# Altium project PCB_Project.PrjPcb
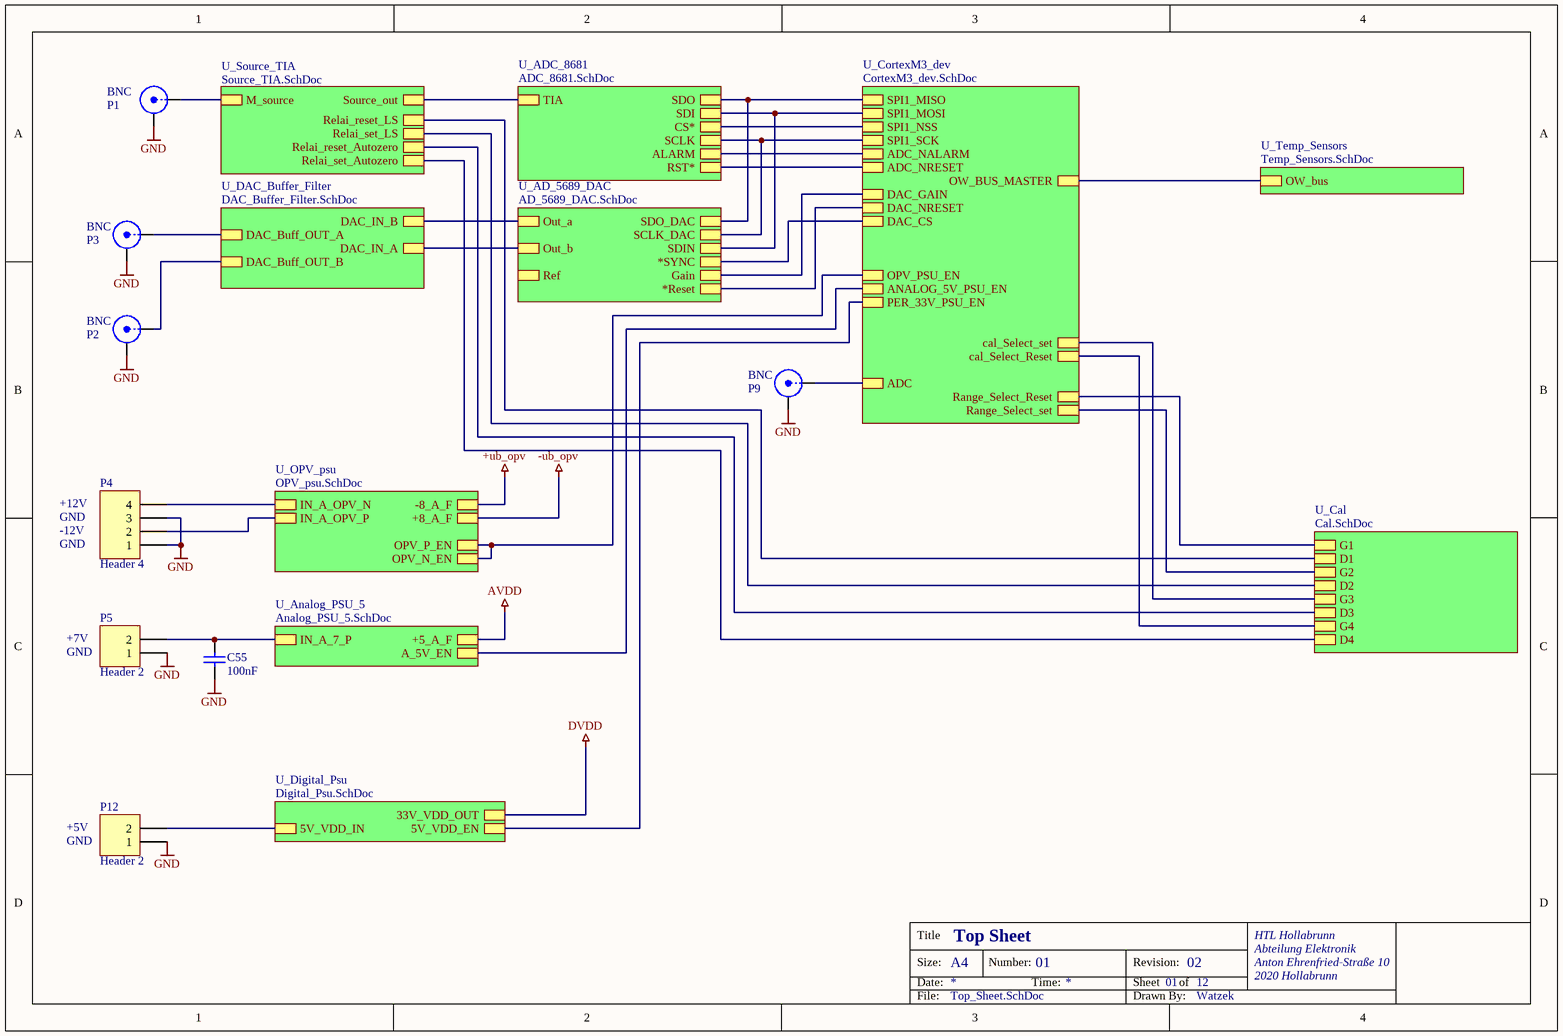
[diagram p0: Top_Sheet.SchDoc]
11 sheets, 114 parts. Net scope: hierarchical (ports join the sheet entries above them; power ports are global).
Board file: PCB1.PcbDoc
Sheets:
  Top_Sheet.SchDoc
    U_Source_TIA = Source_TIA.SchDoc
    U_DAC_Buffer_Filter = DAC_Buffer_Filter.SchDoc
    U_ADC_8681 = ADC_8681.SchDoc
    U_AD_5689_DAC = AD_5689_DAC.SchDoc
    U_Temp_Sensors = Temp_Sensors.SchDoc
    U_Digital_Psu = Digital_Psu.SchDoc
    U_Analog_PSU_5 = Analog_PSU_5.SchDoc
    U_OPV_psu = OPV_psu.SchDoc
    U_CortexM3_dev = CortexM3_dev.SchDoc
    U_Cal = Cal.SchDoc

## Sheet Top_Sheet.SchDoc: Top Sheet
size A4; ApprovedBy: Watzek; CheckedBy: Watzek; Author: Watzek; DrawnBy: Watzek; Organization: HTL Hollabrunn; Address1: Abteilung Elektronik; Address2: Anton Ehrenfried-Straße 10; Address3: 2020 Hollabrunn; DocumentNumber: 01; Revision: 02; SheetNumber: 01; SheetTotal: 12; SPICEModelCacheIHPBHSPQ: <root> / <DocumentId>IHPBHSPQ</DocumentId> / <CacheFrame Number="0"> / <Model Name="cap" Kind="MDL"> / <Text>*Default semiconductor capacitor / .MODEL CAP C()</Text> / </Model> / </CacheFrame> / </root>

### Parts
C55  100nF  [C1206-KUE]
P1  BNC  [BNC_RA CON]
P2  BNC  [BNC_RA CON]
P3  BNC  [BNC_RA CON]
P4  Header 4  [HDR1X4]
P5  Header 2  [HDR1X2]
P9  BNC  [BNC_RA CON]
P12  Header 2  [HDR1X2]

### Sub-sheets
U_AD_5689_DAC = AD_5689_DAC.SchDoc: Ref, Out_a, Out_b, SDIN, SDO_DAC, SCLK_DAC, *SYNC, Gain, *Reset
U_ADC_8681 = ADC_8681.SchDoc: SDI, CS*, SCLK, SDO, ALARM, RST*, TIA
U_Analog_PSU_5 = Analog_PSU_5.SchDoc: IN_A_7_P, +5_A_F, A_5V_EN
U_Cal = Cal.SchDoc: G1, G2, D1, D2, G3, D3, G4, D4
U_CortexM3_dev = CortexM3_dev.SchDoc: SPI1_NSS, SPI1_SCK, SPI1_MISO, SPI1_MOSI, ADC_NALARM, ADC_NRESET, DAC_GAIN, DAC_NRESET, DAC_CS, OW_BUS_MASTER, OPV_PSU_EN, ANALOG_5V_PSU_EN, PER_33V_PSU_EN, Range_Select_set, Range_Select_Reset, ADC, cal_Select_Reset, cal_Select_set
U_DAC_Buffer_Filter = DAC_Buffer_Filter.SchDoc: DAC_IN_B, DAC_Buff_OUT_B, DAC_IN_A, DAC_Buff_OUT_A
U_Digital_Psu = Digital_Psu.SchDoc: 5V_VDD_IN, 33V_VDD_OUT, 5V_VDD_EN
U_OPV_psu = OPV_psu.SchDoc: IN_A_OPV_P, +8_A_F, IN_A_OPV_N, -8_A_F, OPV_P_EN, OPV_N_EN
U_Source_TIA = Source_TIA.SchDoc: M_source, Source_out, Relai_set_LS, Relai_reset_LS, Relai_reset_Autozero, Relai_set_Autozero
U_Temp_Sensors = Temp_Sensors.SchDoc: OW_bus

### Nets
GND: C55.1 P1.2(Y) P2.2(Y) P3.2(Y) P4.1 P4.3 P5.1 P9.2(Y) P12.1
M_source: P1.1(X) ; sheet U_Source_TIA/M_source
SPI1_MISO: sheet U_ADC_8681/SDO, sheet U_AD_5689_DAC/SDO_DAC, sheet U_CortexM3_dev/SPI1_MISO
SPI1_MOSI: sheet U_ADC_8681/SDI, sheet U_AD_5689_DAC/SDIN, sheet U_CortexM3_dev/SPI1_MOSI
SPI1_SCK: sheet U_ADC_8681/SCLK, sheet U_AD_5689_DAC/SCLK_DAC, sheet U_CortexM3_dev/SPI1_SCK
NetC36_2: P12.2 ; sheet U_Digital_Psu/5V_VDD_IN
NetC47_2: P4.2 ; sheet U_OPV_psu/IN_A_OPV_P
NetC49_2: P4.4 ; sheet U_OPV_psu/IN_A_OPV_N
NetC55_2: C55.2 P5.2 ; sheet U_Analog_PSU_5/IN_A_7_P
NetD5_2: sheet U_Source_TIA/Relai_set_LS, sheet U_Cal/D2
NetD6_2: sheet U_Source_TIA/Relai_reset_LS, sheet U_Cal/D1
NetD7_2: sheet U_Source_TIA/Relai_reset_Autozero, sheet U_Cal/D3
NetD8_2: sheet U_Source_TIA/Relai_set_Autozero, sheet U_Cal/D4
NetN3_7: sheet U_Source_TIA/Source_out, sheet U_ADC_8681/TIA
NetN3_11: sheet U_ADC_8681/CS*, sheet U_CortexM3_dev/SPI1_NSS
NetN3_14: sheet U_ADC_8681/ALARM, sheet U_CortexM3_dev/ADC_NALARM
NetN4_1: sheet U_AD_5689_DAC/*Reset, sheet U_CortexM3_dev/DAC_NRESET
NetN4_2: P9.1(X) ; sheet U_CortexM3_dev/ADC
NetN4_3: sheet U_AD_5689_DAC/*SYNC, sheet U_CortexM3_dev/DAC_CS
NetN4_4: sheet U_AD_5689_DAC/Gain, sheet U_CortexM3_dev/DAC_GAIN
NetN4_9: sheet U_CortexM3_dev/cal_Select_set, sheet U_Cal/G3
NetN4_10: sheet U_CortexM3_dev/cal_Select_Reset, sheet U_Cal/G4
NetN4_11: sheet U_CortexM3_dev/Range_Select_set, sheet U_Cal/G2
NetN4_12: sheet U_CortexM3_dev/Range_Select_Reset, sheet U_Cal/G1
NetN4_13: sheet U_OPV_psu/OPV_P_EN, sheet U_OPV_psu/OPV_N_EN, sheet U_CortexM3_dev/OPV_PSU_EN
NetN4_20: sheet U_Analog_PSU_5/A_5V_EN, sheet U_CortexM3_dev/ANALOG_5V_PSU_EN
NetN4_21: sheet U_Temp_Sensors/OW_bus, sheet U_CortexM3_dev/OW_BUS_MASTER
NetN4_23: sheet U_Digital_Psu/5V_VDD_EN, sheet U_CortexM3_dev/PER_33V_PSU_EN
NetN4_27: sheet U_ADC_8681/RST*, sheet U_CortexM3_dev/ADC_NRESET
NetP2_1: P2.1(X) ; sheet U_DAC_Buffer_Filter/DAC_Buff_OUT_B
NetP3_1: P3.1(X) ; sheet U_DAC_Buffer_Filter/DAC_Buff_OUT_A
NetR19_1: sheet U_DAC_Buffer_Filter/DAC_IN_B, sheet U_AD_5689_DAC/Out_a
NetR20_1: sheet U_DAC_Buffer_Filter/DAC_IN_A, sheet U_AD_5689_DAC/Out_b

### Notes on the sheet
- +12V
- GND
- -12V
- +7V
- +5V

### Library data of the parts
C55 = Capacitor: Manufacturer: Kemet; Bezeichnung: Kerko +-10% 63V
P1-P3 P9 = BNC: BNC Elbow Connector
P4 = Header 4: Header, 4-Pin
P5 P12 = Header 2: Header, 2-Pin

## Sheet Source_TIA.SchDoc: TIA and damper
size A4; Author: Watzek; DrawnBy: Watzek; Organization: HTL Hollabrunn; Address1: Abteilung Elektronik; Address2: Anton Ehrenfried-Straße 10; Address3: 2020 Hollabrunn; DocumentNumber: 02; Revision: 02; SheetNumber: 02; SheetTotal: 12; SPICEModelCacheBSQSHVBX: <root> / <DocumentId>BSQSHVBX</DocumentId> / <CacheFrame Number="0"> / <Model Name="cap" Kind="MDL"> / <Text>*Default semiconductor capacitor / .MODEL CAP C()</Text> / </Model> / </CacheFrame> / </root>
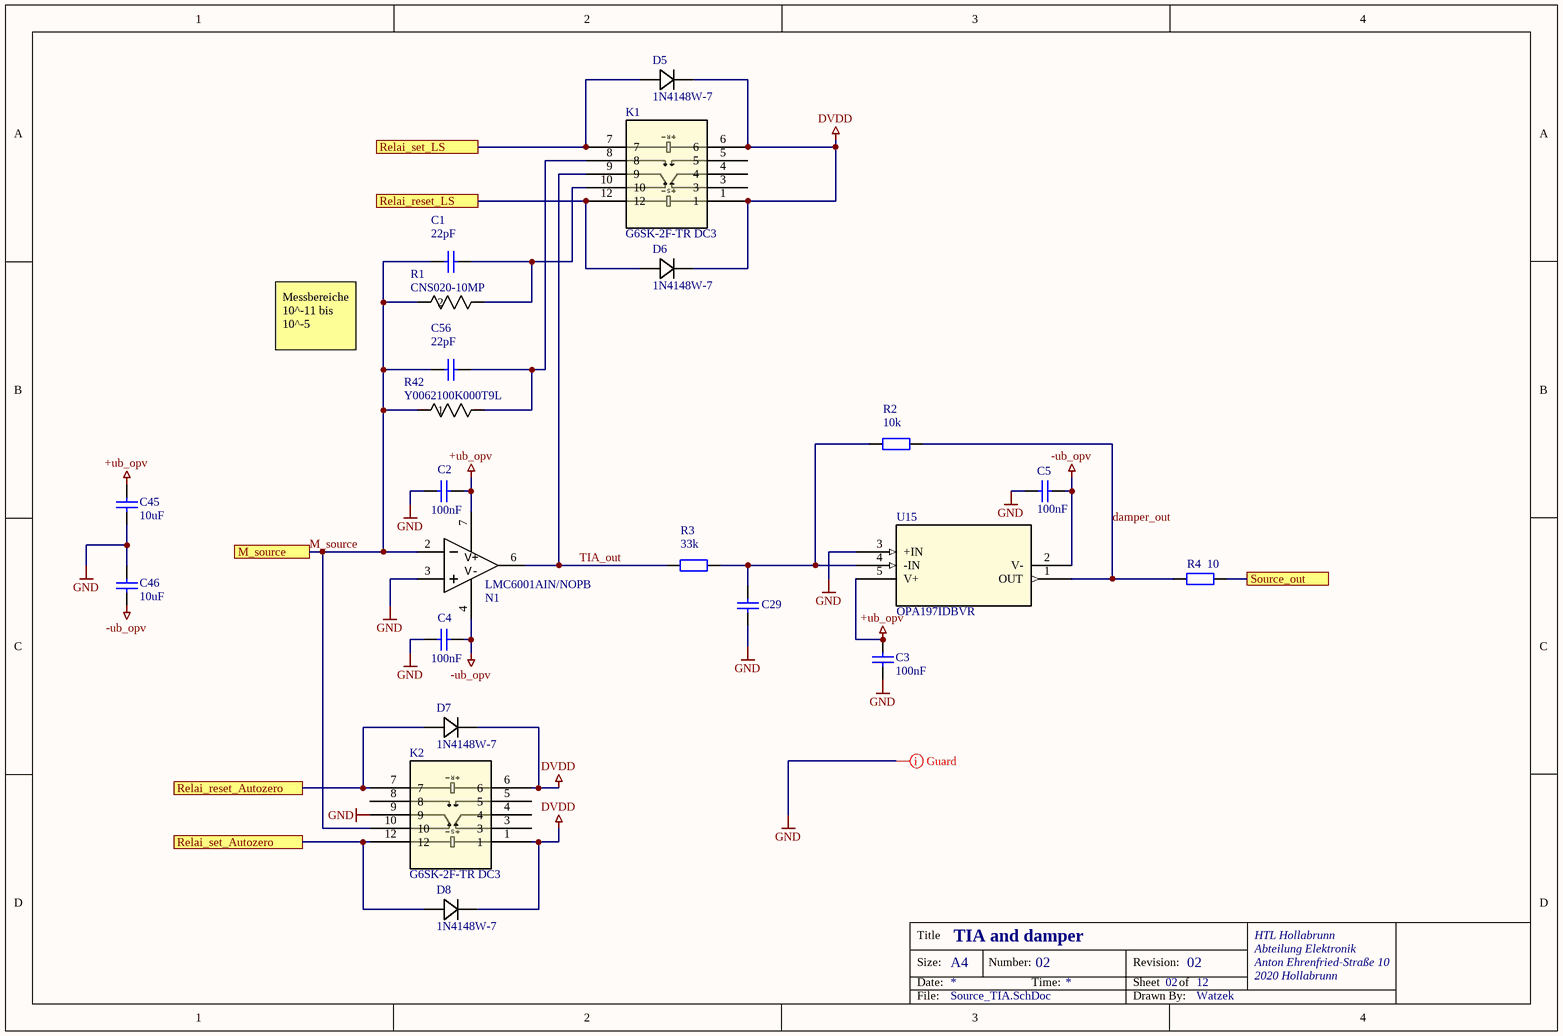
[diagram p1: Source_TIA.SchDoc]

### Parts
C1  22pF  [C1206-KUE]
C2  100nF  [C1206-KUE]
C3  100nF  [C1206-KUE]
C4  100nF  [C1206-KUE]
C5  100nF  [C1206-KUE]
C29  (no value)  [C1206-KUE]
C45  10uF  [C1206-KUE]
C46  10uF  [C1206-KUE]
C56  22pF  [C1206-KUE]
D5  1N4148W-7  [SOD123_DIO]
D6  1N4148W-7  [SOD123_DIO]
D7  1N4148W-7  [SOD123_DIO]
D8  1N4148W-7  [SOD123_DIO]
K1  G6SK-2F-TR DC3  [RELAY_G6SK-2F DC3_OMR]
K2  G6SK-2F-TR DC3  [RELAY_G6SK-2F DC3_OMR]
N1  LMC6001AIN/NOPB  [DIP8]
R1  CNS020-10MP  [RES_CNS020_VIS]
R2  10k  [C1206-KUE]
R3  33k  [C1206-KUE]
R4  10  [C1206-KUE]
R42  Y0062100K000T9L  [RES_S102K_7P62X2P67_VIS]
U15  OPA197IDBVR  [DBV5_TEX]

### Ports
M_source, Relai_reset_Autozero, Relai_reset_LS, Relai_set_Autozero, Relai_set_LS, Source_out

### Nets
+ub_opv: C2.2 C3.2 C45.2 N1.7(V+) U15.5(V+)  [project net neg_out]
-ub_opv: C4.2 C5.2 C46.1 N1.4(V-) U15.2(V-)  [project net pos_out]
DVDD: D5.1 D6.1 D7.1 D8.1 K1.1 K1.6 K2.1 K2.6
GND: C2.1 C3.1 C4.1 C5.1 C29.1 C45.1 C46.2 K2.9 N1.3(IN+) U15.3(+IN)
damper_out: R2.1 R4.2 U15.1(OUT)
M_source: C1.1 C56.1 K2.10 N1.2(IN-) R1.2 R42.1 ; port M_source
TIA_out: K1.9 N1.6(OUT) R3.2
NetC1_2: C1.2 K1.10 R1.1
NetC29_2: C29.2 R2.2 R3.1 U15.4(-IN)
NetC56_2: C56.2 K1.8 R42.2
NetD5_2: D5.2 K1.7 ; port Relai_set_LS
NetD6_2: D6.2 K1.12 ; port Relai_reset_LS
NetD7_2: D7.2 K2.7 ; port Relai_reset_Autozero
NetD8_2: D8.2 K2.12 ; port Relai_set_Autozero
NetN3_7: R4.1 ; port Source_out

Not connected (* = marked no-connect by the designer): K1 3 4 5; K2 3 4 5 8

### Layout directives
mark named Guard: GND

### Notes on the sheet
- Messbereiche 10^-11 bis 10^-5

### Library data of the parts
C1-C5 C29 C45 C46 C56 = Capacitor: as C55 on sheet Top_Sheet
D5-D8 = 1N4148W-7: Description; Manufacturer_Name: Diodes Inc
K1 K2 = G6SK-2F-TR DC3: Description; Manufacturer_Name: Omron
N1 = LMC6001AINNOPB: Ultra-Low Input Current Amplifier 8-PDIP -40 to 85; Manufacturer_Name: Texas Instruments; Manufacturer: NationalSemiconductor; Characteristics: LMC6001AINUltra-LowInputBiasCurrentOpAmp; CompType: OpAmpIC; TaMin_C: -400; TaMax_C: 850; ComponentLink1DescBC: LMC6001Datasheet; ComponentLink2DescA4: LMC6001WebPage; ComponentLink3DescAC: N08EPackageWebPage
R1 = CNS020-10KP: CNS 020 10K 0,02% e2; Manufacturer_Name: Vishay
R2-R4 = ResistorSMD: Resistor SMD; Manufacturer: AVX; Bezeichnung: SMD Wid. 1/8W 2%
R42 = Y0062100K000T9L: No Description Available; Manufacturer_Name: Vishay
U15 = OPA197IDBVR: Single, 36-V, precision, rail-to-rail input output, low offset voltage op amp 5-SOT-23 -40 to 125; Manufacturer_Name: Texas Instruments

## Sheet DAC_Buffer_Filter.SchDoc: DAC Buffer
size A4; DrawnBy: Michael Watzek; Organization: HTL Hollabrunn; Address1: Abteilung Elektronik; Address2: Anton Ehrenfried-Straße 10; Address3: 2020 Hollabrunn; DocumentNumber: 09; Revision: 01; SheetNumber: 09; SheetTotal: 12; SPICEModelCacheDRLOHMHD: <root> / <DocumentId>DRLOHMHD</DocumentId> / <CacheFrame Number="0"> / <Model Name="cap" Kind="MDL"> / <Text>*Default semiconductor capacitor / .MODEL CAP C()</Text> / </Model> / </CacheFrame> / </root>
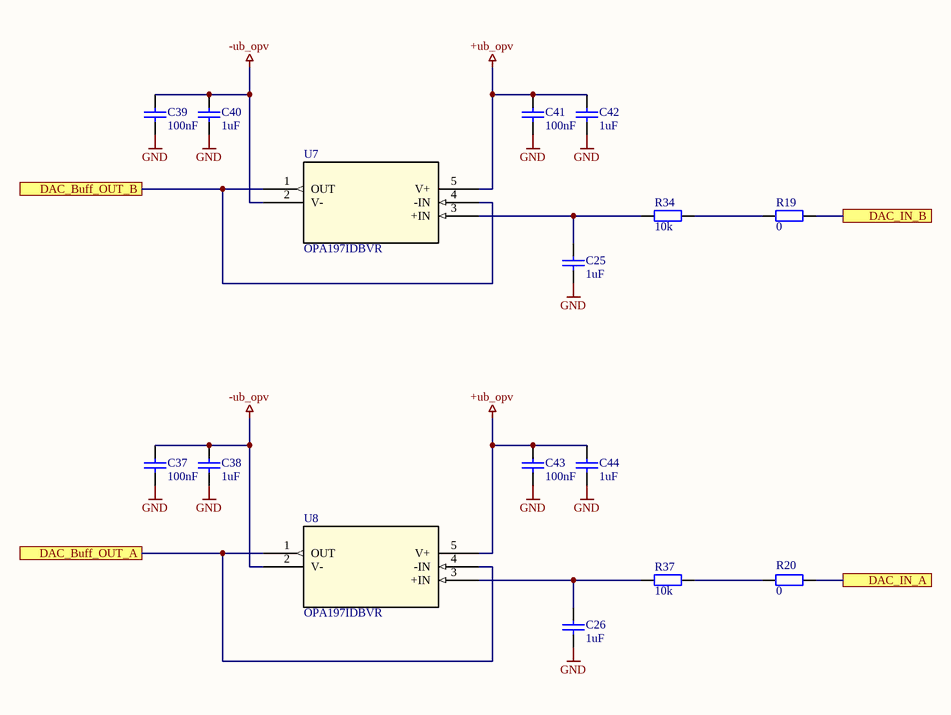
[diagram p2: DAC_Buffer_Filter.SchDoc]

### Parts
C25  1uF  [C1206-KUE]
C26  1uF  [C1206-KUE]
C37  100nF  [C1206-KUE]
C38  1uF  [C1206-KUE]
C39  100nF  [C1206-KUE]
C40  1uF  [C1206-KUE]
C41  100nF  [C1206-KUE]
C42  1uF  [C1206-KUE]
C43  100nF  [C1206-KUE]
C44  1uF  [C1206-KUE]
R19  0  [C1206-KUE]
R20  0  [C1206-KUE]
R34  10k  [C1206-KUE]
R37  10k  [C1206-KUE]
U7  OPA197IDBVR  [DBV5_TEX]
U8  OPA197IDBVR  [DBV5_TEX]

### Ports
DAC_Buff_OUT_A, DAC_Buff_OUT_B, DAC_IN_A, DAC_IN_B

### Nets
+ub_opv: C41.2 C42.2 C43.2 C44.2 U7.5(V+) U8.5(V+)  [project net neg_out]
-ub_opv: C37.2 C38.2 C39.2 C40.2 U7.2(V-) U8.2(V-)  [project net pos_out]
GND: C25.1 C26.1 C37.1 C38.1 C39.1 C40.1 C41.1 C42.1 C43.1 C44.1
NetC25_2: C25.2 R34.2 U7.3(+IN)
NetC26_2: C26.2 R37.2 U8.3(+IN)
NetP2_1: U7.1(OUT) U7.4(-IN) ; port DAC_Buff_OUT_B
NetP3_1: U8.1(OUT) U8.4(-IN) ; port DAC_Buff_OUT_A
NetR19_1: R19.1 ; port DAC_IN_B
NetR19_2: R19.2 R34.1
NetR20_1: R20.1 ; port DAC_IN_A
NetR20_2: R20.2 R37.1

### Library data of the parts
C25 C26 C37-C44 = Capacitor: as C55 on sheet Top_Sheet
R19 R20 R34 R37 = ResistorSMD: as R2 on sheet Source_TIA
U7 U8 = OPA197IDBVR: as U15 on sheet Source_TIA

## Sheet ADC_8681.SchDoc: source ADC
size A4; Author: Watzek; DrawnBy: Watzek; Organization: HTL Hollabrunn; Address1: Abteilung Elektronik; Address2: Anton Ehrenfried-Straße 10; Address3: 2020 Hollabrunn; DocumentNumber: 04; Revision: 01; SheetNumber: 04; SheetTotal: 12; SPICEModelCacheSWPEVHXS: <root> / <DocumentId>SWPEVHXS</DocumentId> / <CacheFrame Number="0"> / <Model Name="cap" Kind="MDL"> / <Text>*Default semiconductor capacitor / .MODEL CAP C()</Text> / </Model> / </CacheFrame> / </root>
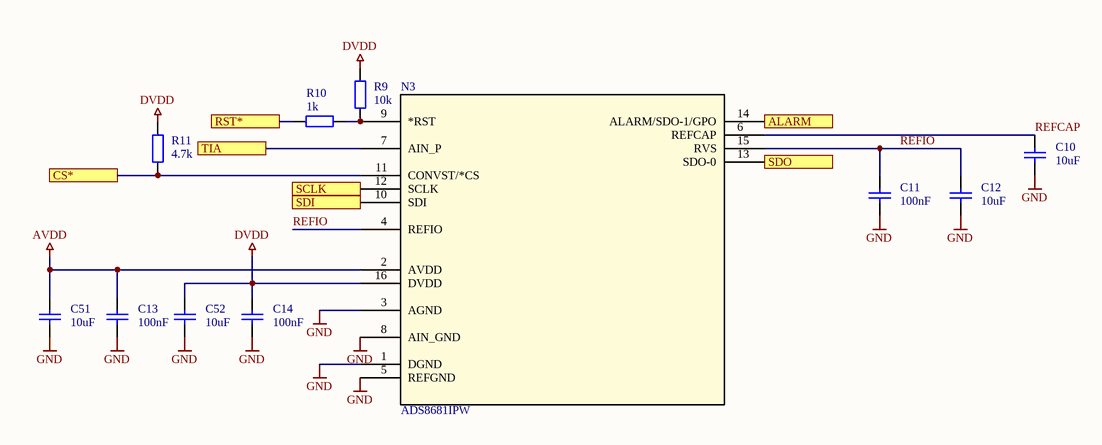
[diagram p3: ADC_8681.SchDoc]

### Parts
C10  10uF  [C1206-KUE]
C11  100nF  [C1206-KUE]
C12  10uF  [C1206-KUE]
C13  100nF  [C1206-KUE]
C14  100nF  [C1206-KUE]
C51  10uF  [C1206-KUE]
C52  10uF  [C1206-KUE]
N3  ADS8681IPW  [PW16_TEX]
R9  10k  [C1206-KUE]
R10  1k  [C1206-KUE]
R11  4.7k  [C1206-KUE]

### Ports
ALARM, CS*, RST*, SCLK, SDI, SDO, TIA

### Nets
AVDD: C13.2 C51.2 N3.2(AVDD)
DVDD: C14.2 C52.2 N3.16(DVDD) R9.1 R11.1
GND: C10.1 C11.1 C12.1 C13.1 C14.1 C51.1 C52.1 N3.1(DGND) N3.3(AGND) N3.5(REFGND) N3.8(AIN_GND)
REFCAP: C10.2 N3.6(REFCAP)
REFIO: C11.2 C12.2 N3.4(REFIO) N3.15(RVS)
SPI1_MISO: N3.13(SDO-0) ; port SDO
SPI1_MOSI: N3.10(SDI) ; port SDI
SPI1_SCK: N3.12(SCLK) ; port SCLK
NetN3_7: N3.7(AIN_P) ; port TIA
NetN3_9: N3.9(*RST) R9.2 R10.2
NetN3_11: N3.11(CONVST/*CS) R11.2 ; port CS*
NetN3_14: N3.14(ALARM/SDO-1/GPO) ; port ALARM
NetN4_27: R10.1 ; port RST*

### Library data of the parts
C10-C14 C51 C52 = Capacitor: as C55 on sheet Top_Sheet
N3 = ADS8681IPW: 16-bit, 1MSPS 1-ch SAR ADC with programmable (Â±12V, Â±10V, Â±6V, Â±5V, Â±2.5V) input ranges on 5V supply 16-TSSOP -40 to 125; Manufacturer_Name: Texas Instruments
R9-R11 = ResistorSMD: as R2 on sheet Source_TIA

## Sheet AD_5689_DAC.SchDoc: DAC for Gate / Drain
size A4; Author: Watzek; DrawnBy: Watzek; Organization: HTL Hollabrunn; Address1: Abteilung Elektronik; Address2: Anton Ehrenfried-Straße 10; Address3: 2020 Hollabrunn; DocumentNumber: 05; Revision: 01; SheetNumber: 05; SheetTotal: 12; SPICEModelCacheXXRROZRR: <root> / <DocumentId>XXRROZRR</DocumentId> / <CacheFrame Number="0"> / <Model Name="cap" Kind="MDL"> / <Text>*Default semiconductor capacitor / .MODEL CAP C()</Text> / </Model> / </CacheFrame> / </root>
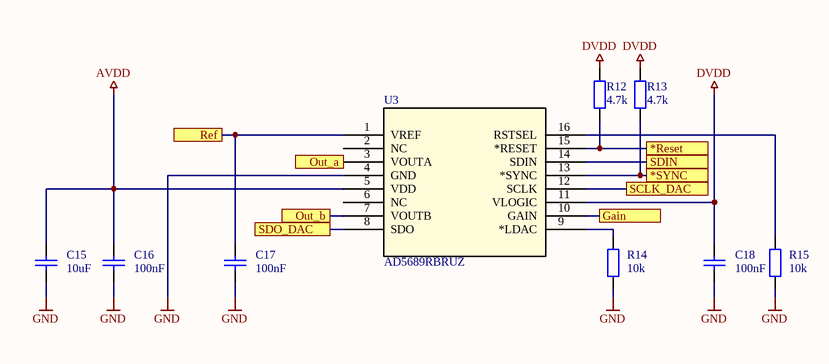
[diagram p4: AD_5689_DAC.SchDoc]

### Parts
C15  10uF  [C1206-KUE]
C16  100nF  [C1206-KUE]
C17  100nF  [C1206-KUE]
C18  100nF  [C1206-KUE]
R12  4.7k  [C1206-KUE]
R13  4.7k  [C1206-KUE]
R14  10k  [C1206-KUE]
R15  10k  [C1206-KUE]
U3  AD5689RBRUZ  [RU_16_ADI]

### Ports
*Reset, *SYNC, Gain, Out_a, Out_b, Ref, SCLK_DAC, SDIN, SDO_DAC

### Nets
AVDD: C15.2 C16.2 U3.5(VDD)
DVDD: C18.2 R12.1 R13.1 U3.11(VLOGIC)
GND: C15.1 C16.1 C17.1 C18.1 R14.2 R15.2 U3.4(GND)
SPI1_MISO: U3.8(SDO) ; port SDO_DAC
SPI1_MOSI: U3.14(SDIN) ; port SDIN
SPI1_SCK: U3.12(SCLK) ; port SCLK_DAC
NetC17_2: C17.2 U3.1(VREF) ; port Ref
NetN4_1: R12.2 U3.15(*RESET) ; port *Reset
NetN4_3: R13.2 U3.13(*SYNC) ; port *SYNC
NetN4_4: U3.10(GAIN) ; port Gain
NetR14_1: R14.1 U3.9(*LDAC)
NetR15_1: R15.1 U3.16(RSTSEL)
NetR19_1: U3.3(VOUTA) ; port Out_a
NetR20_1: U3.7(VOUTB) ; port Out_b

Not connected (* = marked no-connect by the designer): U3 2(NC) 6(NC)

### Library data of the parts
C15-C18 = Capacitor: as C55 on sheet Top_Sheet
R12-R15 = ResistorSMD: as R2 on sheet Source_TIA
U3 = AD5689RBRUZ: Dual, 16-Bit nanoDAC+ with 2 ppm/Â°C Reference, SPI Interface; Manufacturer_Name: Analog Devices Inc

## Sheet Temp_Sensors.SchDoc: One Wire Devices
size A4; DrawnBy: Michael Watzek; Organization: HTL Hollabrunn; Address1: Abteilung Elektronik; Address2: Anton Ehrenfried-Straße 10; Address3: 2020 Hollabrunn; DocumentNumber: 10; Revision: 01; SheetNumber: 10; SheetTotal: 12
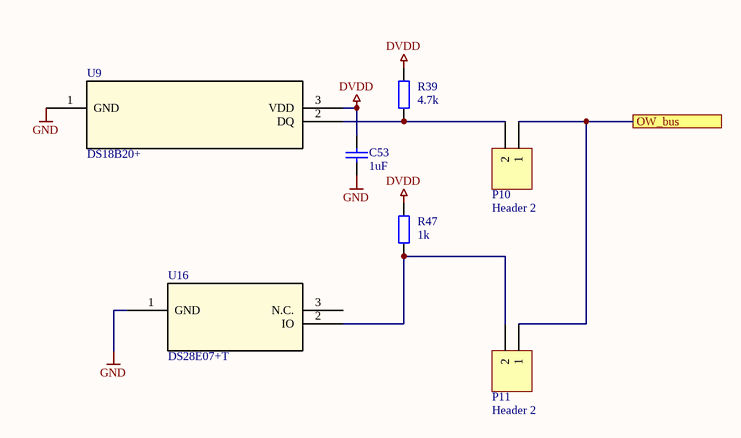
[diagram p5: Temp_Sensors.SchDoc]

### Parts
C53  1uF  [C1206-KUE]
P10  Header 2  [HDR1X2]
P11  Header 2  [HDR1X2]
R39  4.7k  [C1206-KUE]
R47  1k  [C1206-KUE]
U9  DS18B20+  [21-0248A_Q3-1_MXM]
U16  DS28E07+T  [21-0250_Q3+4_MXM]

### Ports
OW_bus

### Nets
DVDD: C53.2 R39.1 R47.1 U9.3(VDD)
GND: C53.1 U9.1(GND) U16.1(GND)
NetN4_21: P10.1 P11.1 ; port OW_bus
NetP10_2: P10.2 R39.2 U9.2(DQ)
NetP11_2: P11.2 R47.2 U16.2(IO)

Not connected (* = marked no-connect by the designer): U16 3(N.C.)

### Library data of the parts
C53 = Capacitor: as C55 on sheet Top_Sheet
P10 P11 = Header 2: Header, 2-Pin
R39 R47 = ResistorSMD: as R2 on sheet Source_TIA
U9 = DS18B20+: Programmable Resolution 1-Wire Digital Thermometer; Manufacturer_Name: Analog Devices Inc
U16 = DS28E07+T: 1024-Bit, 1-Wire EEPROM; Manufacturer_Name: Analog Devices Inc

## Sheet Digital_Psu.SchDoc: Digital PSU
size A4; DrawnBy: Michael Watzek; Organization: HTL Hollabrunn; Address1: Abteilung Elektronik; Address2: Anton Ehrenfried-Straße 10; Address3: 2020 Hollabrunn; DocumentNumber: 07; Revision: 02; SheetNumber: 07; SheetTotal: 12; SPICEModelCacheAWIPVUZH: <root> / <DocumentId>AWIPVUZH</DocumentId> / <CacheFrame Number="0"> / <Model Name="cap" Kind="MDL"> / <Text>*Default semiconductor capacitor / .MODEL CAP C()</Text> / </Model> / </CacheFrame> / </root>
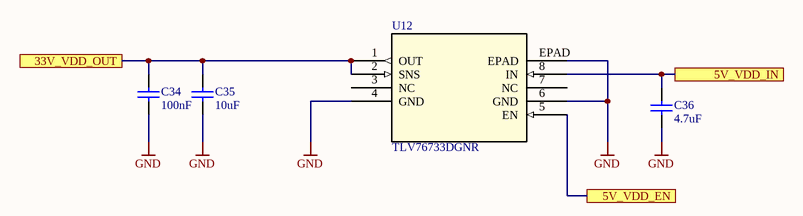
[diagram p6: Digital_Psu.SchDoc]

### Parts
C34  100nF  [C1206-KUE]
C35  10uF  [C1206-KUE]
C36  4.7uF  [C1206-KUE]
U12  TLV76733DGNR  [VSSOP8_DGN_TEX]

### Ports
5V_VDD_EN, 5V_VDD_IN, 33V_VDD_OUT

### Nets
DVDD: C34.2 C35.2 U12.1(OUT) U12.2(SNS) ; port 33V_VDD_OUT
GND: C34.1 C35.1 C36.1 U12.4(GND) U12.6(GND) U12.EPAD
NetC36_2: C36.2 U12.8(IN) ; port 5V_VDD_IN
NetN4_23: U12.5(EN) ; port 5V_VDD_EN

Not connected (* = marked no-connect by the designer): U12 3(NC) 7(NC)

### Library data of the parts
C34-C36 = Capacitor: as C55 on sheet Top_Sheet
U12 = TLV76733DGNR: Adjustable- and fixed-output, 1-A, 16-V, positive-voltage low-dropout (LDO) linear regulator 8-HVSSOP -40 to 125; Manufacturer_Name: Texas Instruments

## Sheet Analog_PSU_5.SchDoc: Analog PSU
size A4; DrawnBy: Michael Watzek; Organization: HTL Hollabrunn; Address1: Abteilung Elektronik; Address2: Anton Ehrenfried-Straße 10; Address3: 2020 Hollabrunn; DocumentNumber: 11; Revision: 02; SheetNumber: 11; SheetTotal: 12; SPICEModelCacheRYPOANGS: <root> / <DocumentId>RYPOANGS</DocumentId> / <CacheFrame Number="0"> / <Model Name="cap" Kind="MDL"> / <Text>*Default semiconductor capacitor / .MODEL CAP C()</Text> / </Model> / </CacheFrame> / </root>
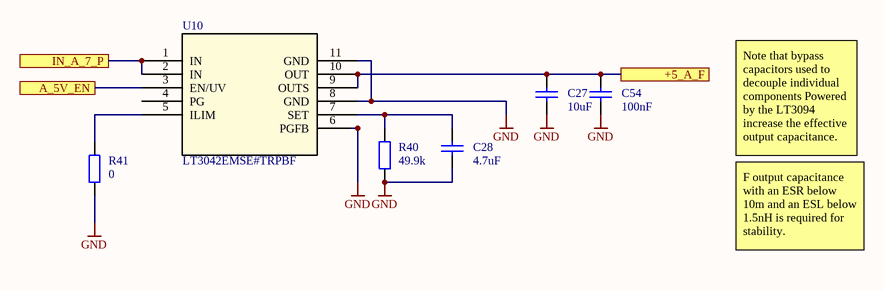
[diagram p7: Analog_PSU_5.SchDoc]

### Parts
C27  10uF  [C1206-KUE]
C28  4.7uF  [C1206-KUE]
C54  100nF  [C1206-KUE]
R40  49.9k  [C1206-KUE]
R41  0  [C1206-KUE]
U10  LT3042EMSE#TRPBF  [05-08-1664_ADI]

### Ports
+5_A_F, A_5V_EN, IN_A_7_P

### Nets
AVDD: C27.2 C54.2 U10.9(OUTS) U10.10(OUT) ; port +5_A_F
GND: C27.1 C28.1 C54.1 R40.2 R41.2 U10.6(PGFB) U10.8(GND) U10.11(GND)
NetC28_2: C28.2 R40.1 U10.7(SET)
NetC55_2: U10.1(IN) U10.2(IN) ; port IN_A_7_P
NetN4_20: U10.3(EN/UV) ; port A_5V_EN
NetR41_1: R41.1 U10.5(ILIM)

Not connected (* = marked no-connect by the designer): U10 4(PG)

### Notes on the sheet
- Note that bypass capacitors used to decouple individual components Powered by the LT3094 increase the effective output capacitance.
- F output capacitance with an ESR below 10m and an ESL below 1.5nH is required for stability.

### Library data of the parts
C27 C28 C54 = Capacitor: as C55 on sheet Top_Sheet
R40 R41 = ResistorSMD: as R2 on sheet Source_TIA
U10 = LT3042EMSETRPBF: 20V, 200mA, Ultralow Noise, Ultrahigh PSRR RF Linear Regulator; Manufacturer_Name: Analog Devices Inc

## Sheet OPV_psu.SchDoc: OPV Power supply
size A4; DrawnBy: Watzek; Organization: HTL Hollabrunn; Address1: Abteilung Elektronik; Address2: Anton Ehrenfried-Straße 10; Address3: 2020 Hollabrunn; DocumentNumber: 03; Revision: 01; SheetNumber: 03; SheetTotal: 12; SPICEModelCacheVBIYTPZR: <root> / <DocumentId>VBIYTPZR</DocumentId> / <CacheFrame Number="0"> / <Model Name="cap" Kind="MDL"> / <Text>*Default semiconductor capacitor / .MODEL CAP C()</Text> / </Model> / </CacheFrame> / </root>
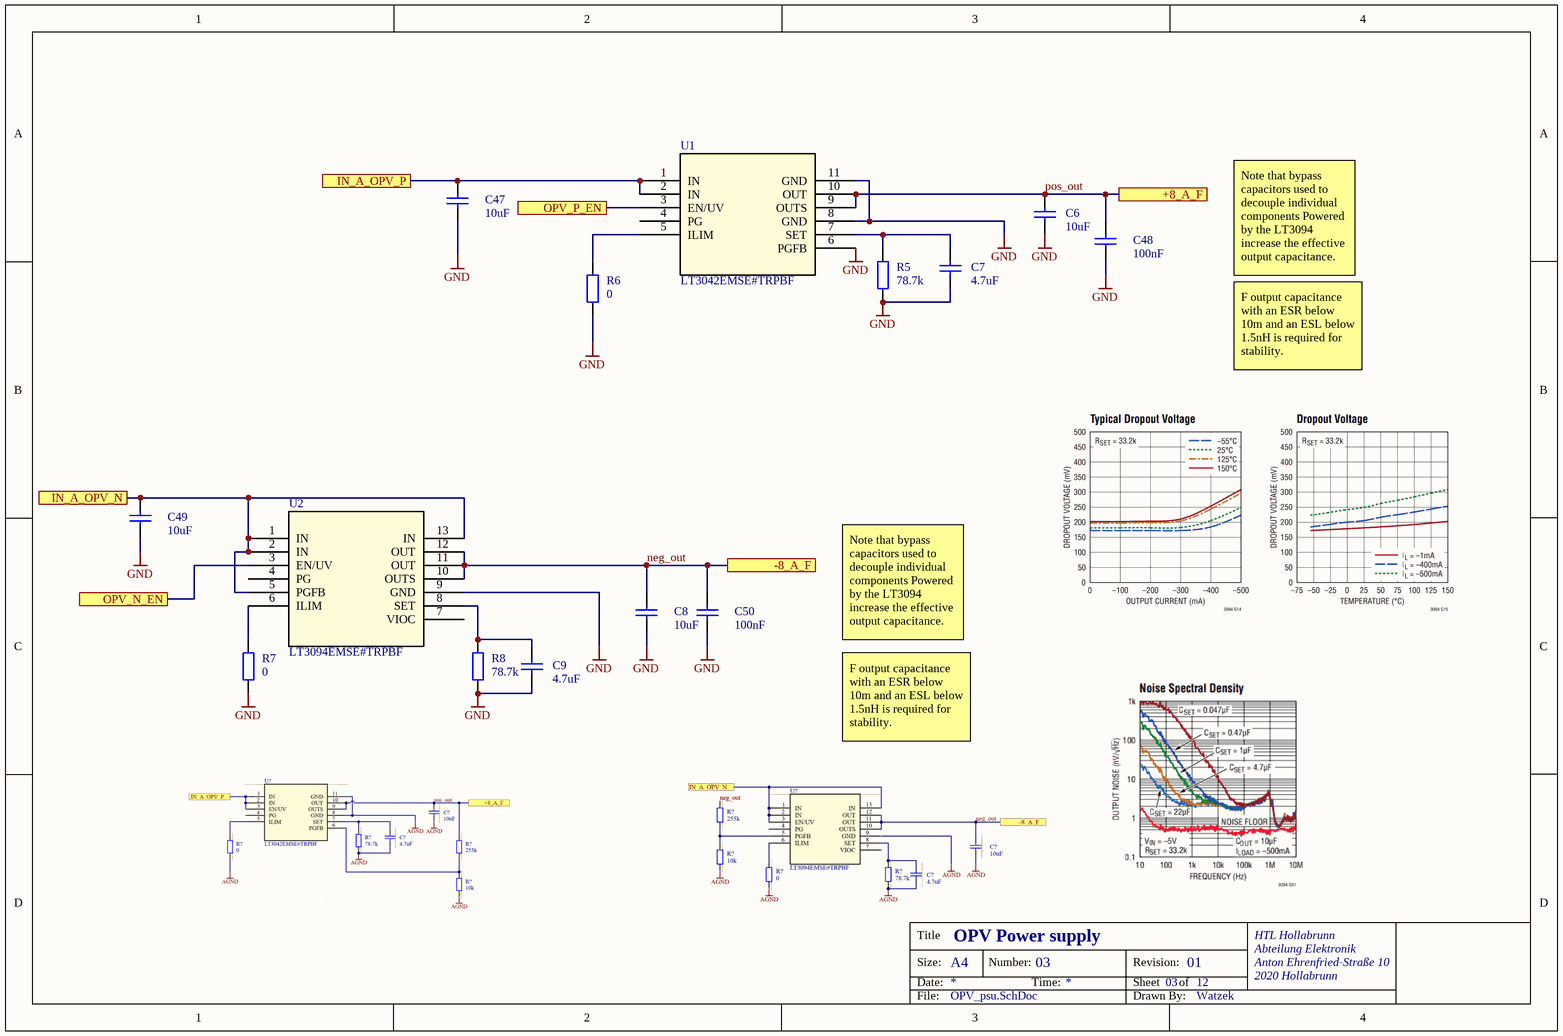
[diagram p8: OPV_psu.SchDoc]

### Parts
C6  10uF  [C1206-KUE]
C7  4.7uF  [C1206-KUE]
C8  10uF  [C1206-KUE]
C9  4.7uF  [C1206-KUE]
C47  10uF  [C1206-KUE]
C48  100nF  [C1206-KUE]
C49  10uF  [C1206-KUE]
C50  100nF  [C1206-KUE]
R5  78.7k  [C1206-KUE]
R6  0  [C1206-KUE]
R7  0  [C1206-KUE]
R8  78.7k  [C1206-KUE]
U1  LT3042EMSE#TRPBF  [05-08-1664_ADI]
U2  LT3094EMSE#TRPBF  [MSE_05-08-1666_ADI]

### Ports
+8_A_F, -8_A_F, IN_A_OPV_N, IN_A_OPV_P, OPV_N_EN, OPV_P_EN

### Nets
GND: C6.1 C7.1 C8.1 C9.1 C47.1 C48.1 C49.1 C50.1 R5.2 R6.2 R7.2 R8.2 U1.6(PGFB) U1.8(GND) U1.11(GND) U2.9(GND)
neg_out: C8.2 C50.2 U2.10(OUTS) U2.11(OUT) U2.12(OUT) ; port -8_A_F
pos_out: C6.2 C48.2 U1.9(OUTS) U1.10(OUT) ; port +8_A_F
NetC7_2: C7.2 R5.1 U1.7(SET)
NetC9_2: C9.2 R8.1 U2.8(SET)
NetC47_2: C47.2 U1.1(IN) U1.2(IN) ; port IN_A_OPV_P
NetC49_2: C49.2 U2.1(IN) U2.2(IN) U2.5(PGFB) U2.13(IN) ; port IN_A_OPV_N
NetN4_13: U1.3(EN/UV) U2.3(EN/UV) ; port OPV_P_EN, port OPV_N_EN
NetR6_1: R6.1 U1.5(ILIM)
NetR7_1: R7.1 U2.6(ILIM)

Not connected (* = marked no-connect by the designer): U1 4(PG); U2 4(PG) 7(VIOC)

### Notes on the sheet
- Note that bypass capacitors used to decouple individual components Powered by the LT3094 increase the effective output capacitance.
- F output capacitance with an ESR below 10m and an ESL below 1.5nH is required for stability.

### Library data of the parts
C6-C9 C47-C50 = Capacitor: as C55 on sheet Top_Sheet
R5-R8 = ResistorSMD: as R2 on sheet Source_TIA
U1 = LT3042EMSETRPBF: as U10 on sheet Analog_PSU_5
U2 = LT3094EMSETRPBF: âˆ’20V, 500mA, Ultralow Noise, Ultrahigh PSRR Negative Linear Regulator; Manufacturer_Name: Analog Devices Inc

## Sheet CortexM3_dev.SchDoc: Cortex M3 Dev and Memory
size A4; DrawnBy: Watzek; Organization: HTL Hollabrunn; Address1: Abteilung Elektronik; Address2: Anton Ehrenfried-Straße 10; Address3: 2020 Hollabrunn; DocumentNumber: 06; Revision: 01; SheetNumber: 06; SheetTotal: 12; SPICEModelCacheGTJPSRCJ: <root> / <DocumentId>GTJPSRCJ</DocumentId> / <CacheFrame Number="0"> / <Model Name="led0" Kind="MDL"> / <Text>*Typ INFRARED GaAs LED: Vf=1.2V Vr=5V If=40mA trr=3uS / *LED Pinout: 1=A, 2=K / .MODEL LED0 D (IS=93.5P RS=84M N=2.63 BV=5 IBV=10U / + CJO=2.97P VJ=.75 M=.333 TT=4.32U)</Text> / </Model> / </CacheFrame> / </root>
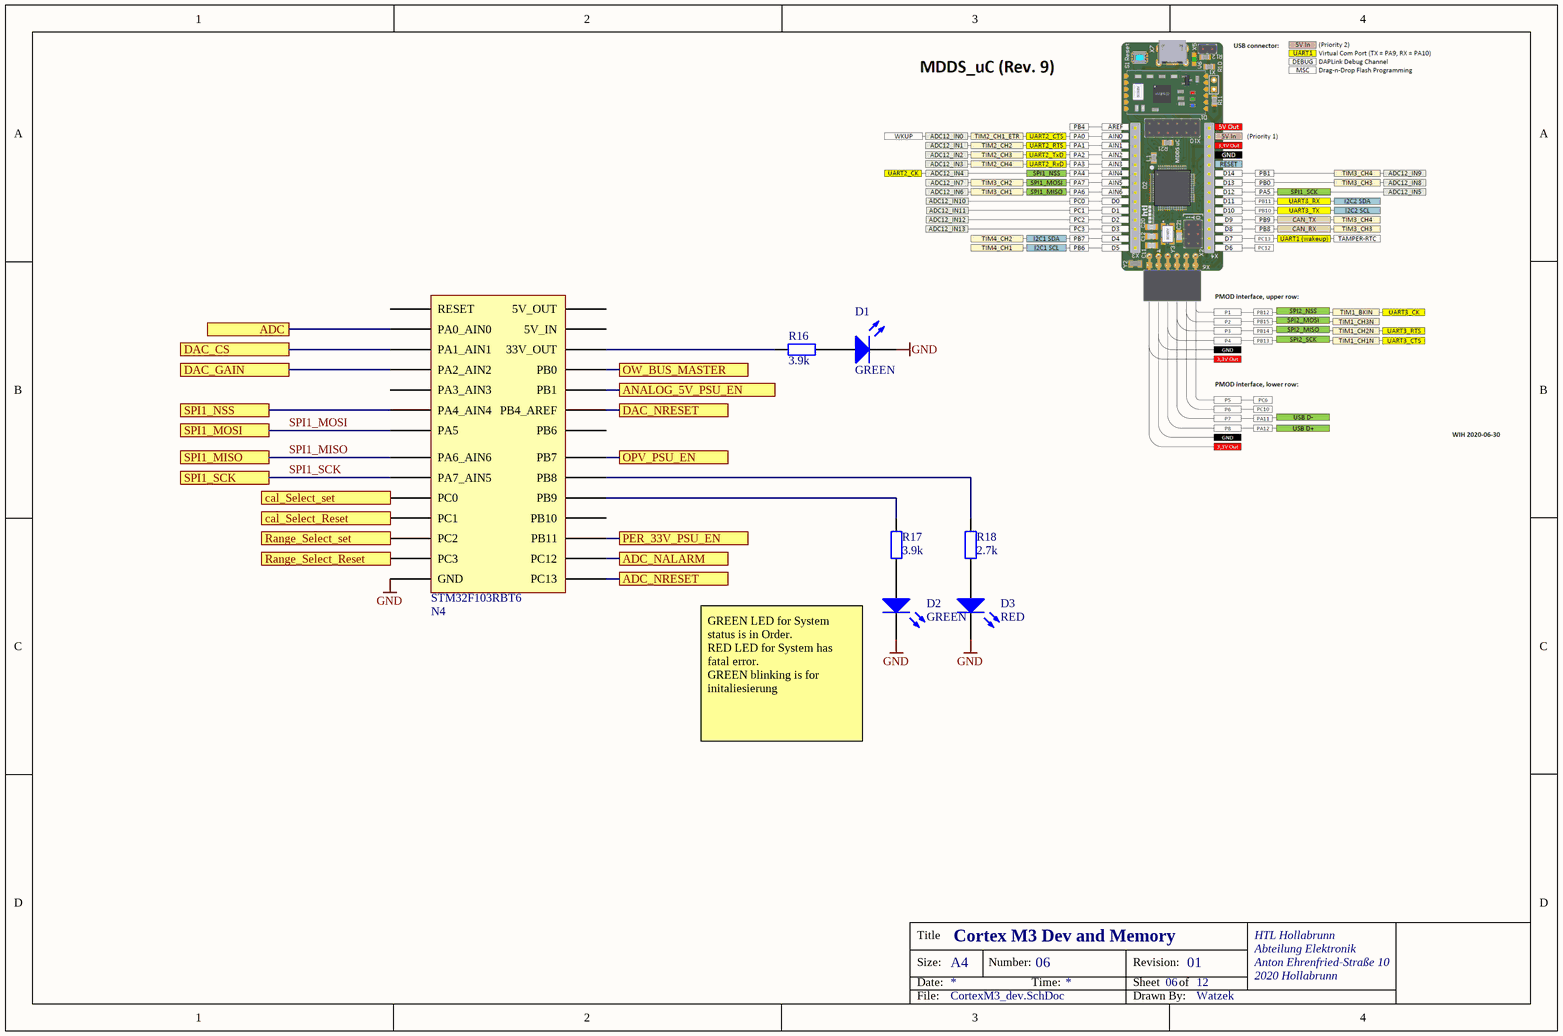
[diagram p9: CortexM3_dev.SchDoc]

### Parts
D1  GREEN  [6-0805_N-KUE]
D2  GREEN  [6-0805_N-KUE]
D3  RED  [6-0805_N-KUE]
N4  STM32F103  [DIP28]  (value not drawn)
R16  3.9k  [C1206-KUE]
R17  3.9k  [C1206-KUE]
R18  2.7k  [C1206-KUE]

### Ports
ADC, ADC_NALARM, ADC_NRESET, ANALOG_5V_PSU_EN, cal_Select_Reset, cal_Select_set, DAC_CS, DAC_GAIN, DAC_NRESET, OPV_PSU_EN, OW_BUS_MASTER, PER_33V_PSU_EN, Range_Select_Reset, Range_Select_set, SPI1_MISO, SPI1_MOSI, SPI1_NSS, SPI1_SCK

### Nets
GND: D1.2(K) D2.2(K) D3.2(K) N4.18(GND)
SPI1_MISO: N4.8(PA6_AIN6) ; port SPI1_MISO
SPI1_MOSI: N4.22(PA5) ; port SPI1_MOSI
SPI1_SCK: N4.7(PA7_AIN5) ; port SPI1_SCK
NetD1_1: D1.1(A) R16.2
NetD2_1: D2.1(A) R17.2
NetD3_1: D3.1(A) R18.2
NetN3_11: N4.6(PA4_AIN4) ; port SPI1_NSS
NetN3_14: N4.28(PC12) ; port ADC_NALARM
NetN4_1: N4.1(PB4_AREF) ; port DAC_NRESET
NetN4_2: N4.2(PA0_AIN0) ; port ADC
NetN4_3: N4.3(PA1_AIN1) ; port DAC_CS
NetN4_4: N4.4(PA2_AIN2) ; port DAC_GAIN
NetN4_9: N4.9(PC0) ; port cal_Select_set
NetN4_10: N4.10(PC1) ; port cal_Select_Reset
NetN4_11: N4.11(PC2) ; port Range_Select_set
NetN4_12: N4.12(PC3) ; port Range_Select_Reset
NetN4_13: N4.13(PB7) ; port OPV_PSU_EN
NetN4_17: N4.17(33V_OUT) R16.1
NetN4_20: N4.20(PB1) ; port ANALOG_5V_PSU_EN
NetN4_21: N4.21(PB0) ; port OW_BUS_MASTER
NetN4_23: N4.23(PB11) ; port PER_33V_PSU_EN
NetN4_25: N4.25(PB9) R17.1
NetN4_26: N4.26(PB8) R18.1
NetN4_27: N4.27(PC13) ; port ADC_NRESET

Not connected (* = marked no-connect by the designer): N4 5(PA3_AIN3) 14(PB6) 15(5V_OUT) 16(5V_IN) 19(RESET) 24(PB10)

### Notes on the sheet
- (near D2) GREEN LED for System status is in Order.
  RED LED for System has fatal error.
  GREEN blinking is for initaliesierung

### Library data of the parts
D1-D3 = LED0: Typical INFRARED GaAs LED
R16-R18 = ResistorSMD: as R2 on sheet Source_TIA

## Sheet Cal.SchDoc: Relai MOSFET Controller
size A4; DrawnBy: Michael Watzek; Organization: HTL Hollabrunn; Address1: Abteilung Elektronik; Address2: Anton Ehrenfried-Straße 10; Address3: 2020 Hollabrunn; DocumentNumber: 12; Revision: 01; SheetNumber: 12; SheetTotal: 12
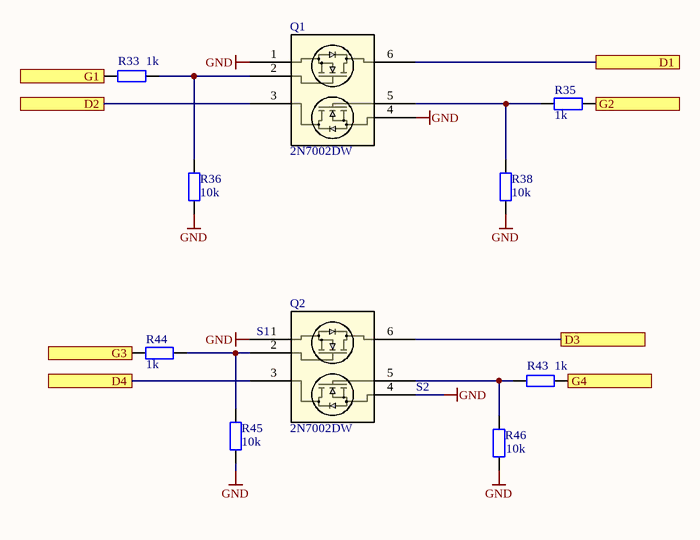
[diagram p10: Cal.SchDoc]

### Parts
Q1  2N7002DW  [SC-88SC70-6SOT-363_419B-02_ONS_OSI]
Q2  2N7002DW  [SC-88SC70-6SOT-363_419B-02_ONS_OSI]
R33  1k  [C1206-KUE]
R35  1k  [C1206-KUE]
R36  10k  [C1206-KUE]
R38  10k  [C1206-KUE]
R43  1k  [C1206-KUE]
R44  1k  [C1206-KUE]
R45  10k  [C1206-KUE]
R46  10k  [C1206-KUE]

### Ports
D1, D2, D3, D4, G1, G2, G3, G4

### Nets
GND: Q1.1 Q1.4 Q2.1 Q2.4 R36.2 R38.2 R45.2 R46.2
NetD5_2: Q1.3 ; port D2
NetD6_2: Q1.6 ; port D1
NetD7_2: Q2.6 ; port D3
NetD8_2: Q2.3 ; port D4
NetN4_9: R44.2 ; port G3
NetN4_10: R43.1 ; port G4
NetN4_11: R35.2 ; port G2
NetN4_12: R33.2 ; port G1
NetQ1_2: Q1.2 R33.1 R36.1
NetQ1_5: Q1.5 R35.1 R38.1
NetQ2_2: Q2.2 R44.1 R45.1
NetQ2_5: Q2.5 R43.2 R46.1

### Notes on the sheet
- (near Q2) S1
- (near Q2) S2

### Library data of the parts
Q1 Q2 = 2N7002DW: Description; Manufacturer_Name: onsemi
R33 R35 R36 R38 R43-R46 = ResistorSMD: as R2 on sheet Source_TIA

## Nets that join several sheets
AVDD: ADC_8681 (C13.2 C51.2 N3.2), AD_5689_DAC (C15.2 C16.2 U3.5), Analog_PSU_5 (C27.2 C54.2 U10.9 U10.10)
DVDD: Source_TIA (8 pins), ADC_8681 (5 pins), AD_5689_DAC (C18.2 R12.1 R13.1 U3.11), Temp_Sensors (C53.2 R39.1 R47.1 U9.3), Digital_Psu (C34.2 C35.2 U12.1 U12.2)
GND: Top_Sheet (9 pins), Source_TIA (10 pins), DAC_Buffer_Filter (10 pins), ADC_8681 (11 pins), AD_5689_DAC (7 pins), Temp_Sensors (C53.1 U9.1 U16.1), Digital_Psu (6 pins), Analog_PSU_5 (8 pins), OPV_psu (16 pins), CortexM3_dev (D1.2 D2.2 D3.2 N4.18), Cal (8 pins)
neg_out: Source_TIA (5 pins), DAC_Buffer_Filter (6 pins), OPV_psu (5 pins)
pos_out: Source_TIA (5 pins), DAC_Buffer_Filter (6 pins), OPV_psu (C6.2 C48.2 U1.9 U1.10)
M_source: Top_Sheet (P1.1), Source_TIA (6 pins)
NetC36_2: Top_Sheet (P12.2), Digital_Psu (C36.2 U12.8)
NetC47_2: Top_Sheet (P4.2), OPV_psu (C47.2 U1.1 U1.2)
NetC49_2: Top_Sheet (P4.4), OPV_psu (5 pins)
NetC55_2: Top_Sheet (C55.2 P5.2), Analog_PSU_5 (U10.1 U10.2)
NetD5_2: Source_TIA (D5.2 K1.7), Cal (Q1.3)
NetD6_2: Source_TIA (D6.2 K1.12), Cal (Q1.6)
NetD7_2: Source_TIA (D7.2 K2.7), Cal (Q2.6)
NetD8_2: Source_TIA (D8.2 K2.12), Cal (Q2.3)
NetN3_7: Source_TIA (R4.1), ADC_8681 (N3.7)
NetN3_11: ADC_8681 (N3.11 R11.2), CortexM3_dev (N4.6)
NetN3_14: ADC_8681 (N3.14), CortexM3_dev (N4.28)
NetN4_1: AD_5689_DAC (R12.2 U3.15), CortexM3_dev (N4.1)
NetN4_2: Top_Sheet (P9.1), CortexM3_dev (N4.2)
NetN4_3: AD_5689_DAC (R13.2 U3.13), CortexM3_dev (N4.3)
NetN4_4: AD_5689_DAC (U3.10), CortexM3_dev (N4.4)
NetN4_9: CortexM3_dev (N4.9), Cal (R44.2)
NetN4_10: CortexM3_dev (N4.10), Cal (R43.1)
NetN4_11: CortexM3_dev (N4.11), Cal (R35.2)
NetN4_12: CortexM3_dev (N4.12), Cal (R33.2)
NetN4_13: OPV_psu (U1.3 U2.3), CortexM3_dev (N4.13)
NetN4_20: Analog_PSU_5 (U10.3), CortexM3_dev (N4.20)
NetN4_21: Temp_Sensors (P10.1 P11.1), CortexM3_dev (N4.21)
NetN4_23: Digital_Psu (U12.5), CortexM3_dev (N4.23)
NetN4_27: ADC_8681 (R10.1), CortexM3_dev (N4.27)
NetP2_1: Top_Sheet (P2.1), DAC_Buffer_Filter (U7.1 U7.4)
NetP3_1: Top_Sheet (P3.1), DAC_Buffer_Filter (U8.1 U8.4)
NetR19_1: DAC_Buffer_Filter (R19.1), AD_5689_DAC (U3.3)
NetR20_1: DAC_Buffer_Filter (R20.1), AD_5689_DAC (U3.7)
SPI1_MISO: ADC_8681 (N3.13), AD_5689_DAC (U3.8), CortexM3_dev (N4.8)
SPI1_MOSI: ADC_8681 (N3.10), AD_5689_DAC (U3.14), CortexM3_dev (N4.22)
SPI1_SCK: ADC_8681 (N3.12), AD_5689_DAC (U3.12), CortexM3_dev (N4.7)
